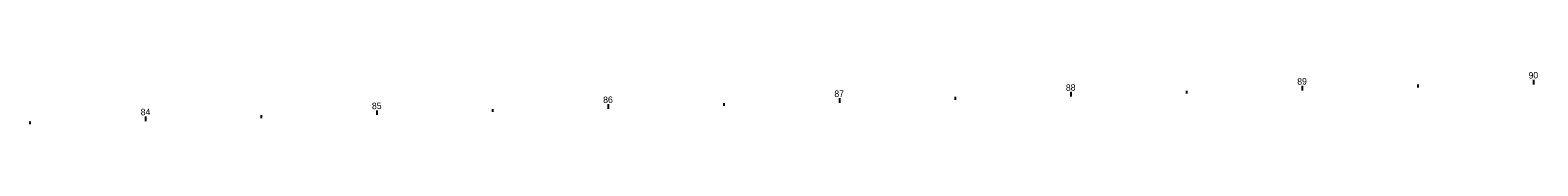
# Model space of a CAD drawing. Extents: x 2402033 to 2407435, y 498456 to 498900.
# Drawn here: x 2405384 to 2406035, y 498729 to 498751 of the extents above; entities that cross this region are included whole.
import ezdxf

# ---------------------------------------------------------------- set-up
doc = ezdxf.new("R2010")
doc.units = 0
for name, color, linetype in [('DR_P_Ditch', 7, 'Continuous'), ('RW_P_Esmt_CH', 7, 'Continuous'), ('RW_X_Esmt_SH', 7, 'Continuous')]:
    doc.layers.add(name, color=color, linetype=linetype)

msp = doc.modelspace()

# ---------------------------------------------------------------- linework, layer by layer
at = {"layer": 'DR_P_Ditch'}
for p, q in [((2406033.41, 498746.01), (2406033.36, 498748.01)), ((2405533.59, 498732.78), (2405533.56, 498733.98))]:
    msp.add_line(p, q, dxfattribs=at)
at = {"layer": 'RW_P_Esmt_CH'}
for p, q in [((2406033.41, 498746.01), (2406033.36, 498748.01)), ((2405833.48, 498740.72), (2405833.45, 498741.92)), ((2405933.45, 498743.37), (2405933.41, 498744.57)), ((2405633.55, 498735.43), (2405633.52, 498736.63)), ((2405733.52, 498738.07), (2405733.49, 498739.27)), ((2405433.62, 498730.13), (2405433.59, 498731.33)), ((2405533.59, 498732.78), (2405533.53, 498734.78))]:
    msp.add_line(p, q, dxfattribs=at)
at = {"layer": 'RW_X_Esmt_SH'}
for p, q in [((2406033.41, 498746.01), (2406033.36, 498748.01)), ((2405833.48, 498740.72), (2405833.43, 498742.72)), ((2405883.46, 498742.04), (2405883.43, 498743.24)), ((2405933.45, 498743.37), (2405933.39, 498745.37)), ((2405983.43, 498744.69), (2405983.4, 498745.89)), ((2405583.57, 498734.1), (2405583.54, 498735.3)), ((2405633.55, 498735.43), (2405633.5, 498737.43)), ((2405683.53, 498736.75), (2405683.5, 498737.95)), ((2405733.52, 498738.07), (2405733.46, 498740.07)), ((2405783.5, 498739.4), (2405783.47, 498740.6)), ((2405383.64, 498728.81), (2405383.61, 498730.01)), ((2405433.62, 498730.13), (2405433.57, 498732.13)), ((2405483.6, 498731.46), (2405483.57, 498732.66)), ((2405533.59, 498732.78), (2405533.53, 498734.78))]:
    msp.add_line(p, q, dxfattribs=at)

# ---------------------------------------------------------------- texts
at = {"layer": 'DR_P_Ditch'}
msp.add_text('90', height=2.8, rotation=1.5166, dxfattribs=at).set_placement((2406031.12, 498748.5))
at = {"layer": 'RW_P_Esmt_CH'}
for s, p in [('90', (2406031.12, 498748.5)), ('85', (2405531.33, 498735.26))]:
    msp.add_text(s, height=2.8, rotation=1.5166, dxfattribs=at).set_placement(p)
at = {"layer": 'RW_X_Esmt_SH'}
for s, p in [('89', (2405931.18, 498745.85)), ('90', (2406031.12, 498748.5)), ('87', (2405731.15, 498740.55)), ('88', (2405831.2, 498743.2)), ('84', (2405431.4, 498732.62)), ('85', (2405531.33, 498735.26)), ('86', (2405631.24, 498737.91))]:
    msp.add_text(s, height=2.8, rotation=1.5166, dxfattribs=at).set_placement(p)

doc.saveas('drawing.dxf')
